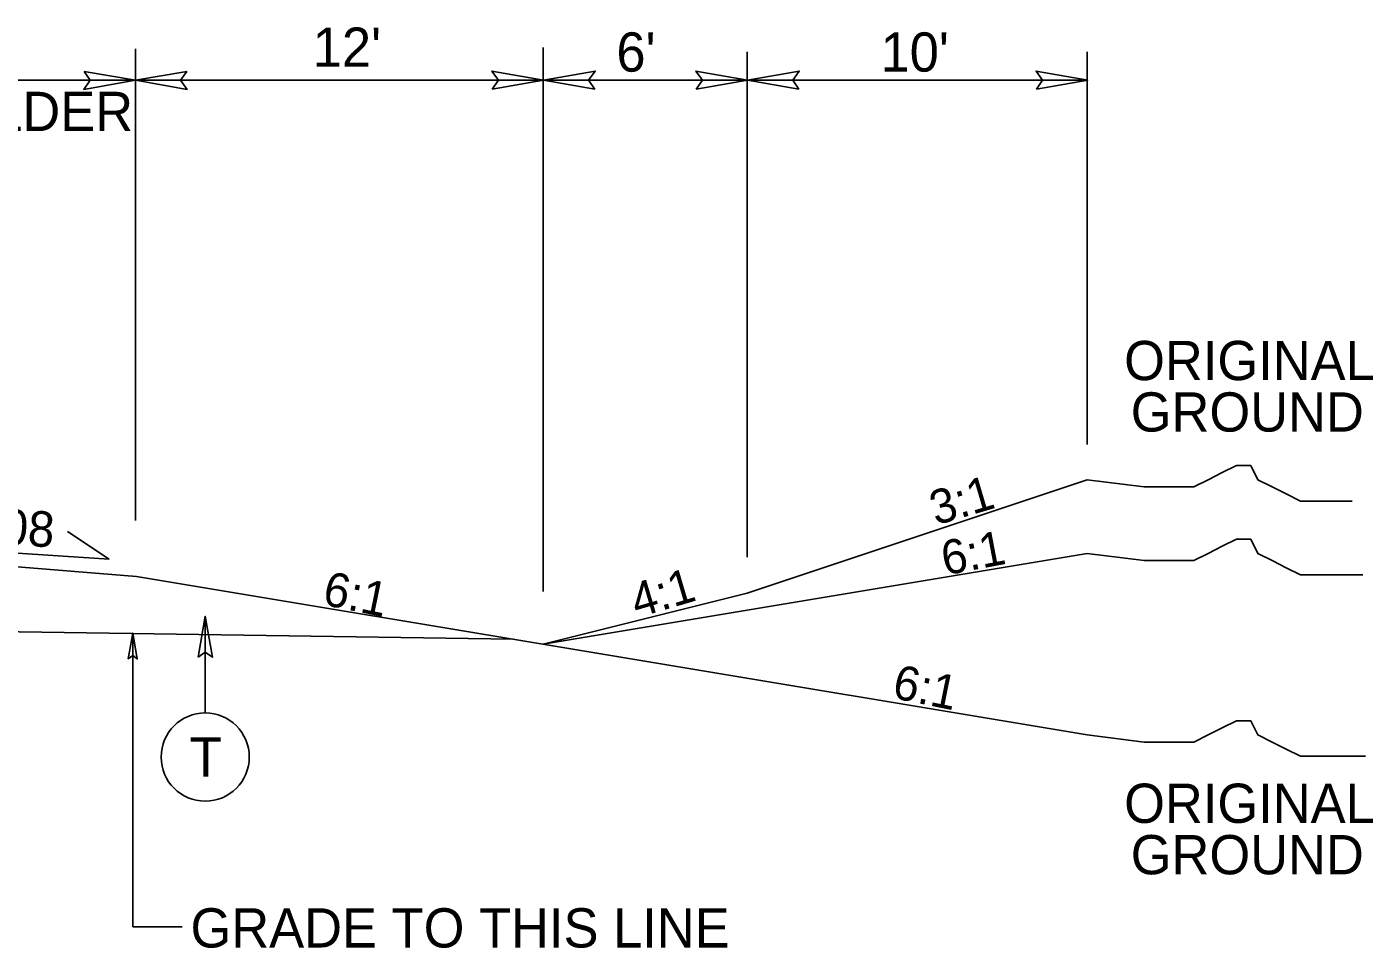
# Model space of a CAD drawing. Extents: x 2176024 to 2177225, y 75947 to 76635.
# Drawn here: x 2177062.27 to 2177101.85, y 76498.99 to 76526.06 of the extents above; entities that cross this region are included whole.
import ezdxf

# ---------------------------------------------------------------- set-up
doc = ezdxf.new("R2010")
doc.units = 0
for name, color, linetype in [('Old_Level_11', 7, 'Continuous'), ('Prop Dimension', 7, 'Continuous'), ('Typical Curb CELL', 7, 'Continuous'), ('Typical Pavement Slope CELL', 7, 'Continuous'), ('Typical Pavement Slope Information CELL', 7, 'Continuous'), ('Typical Shoulder Slope CELL', 7, 'Continuous'), ('Typical Slope Point Local CELL', 7, 'Continuous'), ('Typical Terminator CELL', 7, 'Continuous'), ('Typical Text General CELL', 7, 'Continuous')]:
    doc.layers.add(name, color=color, linetype=linetype)

msp = doc.modelspace()

# ---------------------------------------------------------------- linework, layer by layer
at = {"layer": 'Old_Level_11'}
msp.add_line((2177067.514, 76505.902), (2177067.514, 76508.744), dxfattribs=at)
msp.add_lwpolyline([(2177067.307, 76507.544), (2177067.514, 76508.744), (2177067.727, 76507.537), (2177067.514, 76507.691)], close=True, dxfattribs=at)
msp.add_circle((2177067.514, 76504.606), 1.296, dxfattribs=at)
at = {"layer": 'Prop Dimension'}
for p, q in [((2177065.462, 76511.553), (2177065.462, 76525.42)), ((2177077.449, 76509.465), (2177077.449, 76525.458)), ((2177083.449, 76510.483), (2177083.449, 76525.325)), ((2177093.449, 76513.785), (2177093.449, 76525.325)), ((2177065.462, 76524.493), (2177055.462, 76524.493)), ((2177065.462, 76524.493), (2177077.462, 76524.493)), ((2177077.462, 76524.493), (2177083.462, 76524.493)), ((2177083.462, 76524.493), (2177093.462, 76524.493)), ((2177065.382, 76508.249), (2177065.382, 76499.613)), ((2177066.836, 76499.613), (2177065.382, 76499.613))]:
    msp.add_line(p, q, dxfattribs=at)
at = {"layer": 'Typical Curb CELL'}
msp.add_line((2177076.565, 76508.068), (2177051.603, 76508.439), dxfattribs=at)
at = {"layer": 'Typical Pavement Slope CELL'}
for p, q in [((2177077.449, 76507.92), (2177093.449, 76510.587)), ((2177093.449, 76505.254), (2177065.497, 76509.912))]:
    msp.add_line(p, q, dxfattribs=at)
at = {"layer": 'Typical Pavement Slope Information CELL'}
for q in [(2177063.465, 76511.235), (2177059.944, 76510.729)]:
    msp.add_line((2177064.69, 76510.416), q, dxfattribs=at)
at = {"layer": 'Typical Shoulder Slope CELL'}
for p, q in [((2177083.449, 76509.42), (2177093.449, 76512.754)), ((2177059.462, 76510.395), (2177065.497, 76509.912)), ((2177077.449, 76507.92), (2177083.449, 76509.42))]:
    msp.add_line(p, q, dxfattribs=at)
at = {"layer": 'Typical Slope Point Local CELL'}
for points in [[(2177093.449, 76512.754), (2177095.12, 76512.546), (2177095.537, 76512.546), (2177096.165, 76512.546), (2177096.582, 76512.546), (2177097, 76512.754), (2177097.418, 76512.963), (2177097.835, 76513.173), (2177098.253, 76513.173), (2177098.463, 76512.754), (2177098.88, 76512.546), (2177099.298, 76512.336), (2177099.716, 76512.128), (2177100.133, 76512.128), (2177100.551, 76512.128), (2177100.969, 76512.128), (2177101.24, 76512.128)], [(2177093.449, 76510.587), (2177095.12, 76510.379), (2177095.538, 76510.379), (2177096.165, 76510.379), (2177096.583, 76510.379), (2177097, 76510.587), (2177097.418, 76510.797), (2177097.836, 76511.006), (2177098.253, 76511.006), (2177098.463, 76510.587), (2177098.881, 76510.379), (2177099.298, 76510.169), (2177099.716, 76509.961), (2177100.134, 76509.961), (2177100.551, 76509.961), (2177100.969, 76509.961), (2177101.387, 76509.961), (2177101.55, 76509.961)], [(2177093.449, 76505.254), (2177095.12, 76505.046), (2177095.537, 76505.046), (2177096.165, 76505.046), (2177096.582, 76505.046), (2177097, 76505.254), (2177097.418, 76505.463), (2177097.835, 76505.673), (2177098.253, 76505.673), (2177098.463, 76505.254), (2177098.88, 76505.046), (2177099.298, 76504.836), (2177099.716, 76504.628), (2177100.133, 76504.628), (2177100.551, 76504.628), (2177100.969, 76504.628), (2177101.386, 76504.628), (2177101.627, 76504.628)]]:
    msp.add_lwpolyline(points, dxfattribs=at)
at = {"layer": 'Typical Terminator CELL'}
for points in [[(2177063.952, 76524.752), (2177065.462, 76524.493), (2177063.944, 76524.224), (2177064.137, 76524.493)], [(2177066.972, 76524.752), (2177065.462, 76524.493), (2177066.98, 76524.224), (2177066.787, 76524.493)], [(2177075.952, 76524.233), (2177077.462, 76524.493), (2177075.944, 76524.761), (2177076.137, 76524.493)], [(2177078.972, 76524.233), (2177077.462, 76524.493), (2177078.98, 76524.761), (2177078.787, 76524.493)], [(2177081.952, 76524.233), (2177083.462, 76524.493), (2177081.944, 76524.761), (2177082.137, 76524.493)], [(2177084.972, 76524.233), (2177083.462, 76524.493), (2177084.98, 76524.761), (2177084.787, 76524.493)], [(2177091.952, 76524.233), (2177093.462, 76524.493), (2177091.944, 76524.761), (2177092.137, 76524.493)], [(2177065.252, 76507.494), (2177065.382, 76508.249), (2177065.516, 76507.49), (2177065.382, 76507.586)]]:
    msp.add_lwpolyline(points, close=True, dxfattribs=at)

# ---------------------------------------------------------------- texts
at = {"layer": 'Old_Level_11'}
msp.add_text('T', height=1.16, rotation=359.9997, dxfattribs=at).set_placement((2177067.057, 76504.026))
at = {"layer": 'Typical Pavement Slope Information CELL'}
msp.add_text('0.08', height=1.0429, rotation=356.2199, dxfattribs=at).set_placement((2177060.34, 76510.94))
at = {"layer": 'Typical Slope Point Local CELL'}
for s, rotation, p in [('3:1', 16.4649, (2177088.996, 76511.408)), ('6:1', 10.8168, (2177089.263, 76509.939)), ('6:1', 348.5135, (2177070.931, 76509.089)), ('4:1', 16.4649, (2177080.206, 76508.688)), ('6:1', 348.5135, (2177087.681, 76506.348))]:
    msp.add_text(s, height=1.0064, rotation=rotation, dxfattribs=at).set_placement(p)
at = {"layer": 'Typical Text General CELL'}
for s, height, p in [("12' ", 1.1533, (2177070.676, 76524.888)), ("6'", 1.1533, (2177079.604, 76524.745)), ("10'", 1.1533, (2177087.37, 76524.745)), ('SHOULDER', 1.1533, (2177056.825, 76523)), ('ORIGINAL', 1.1533, (2177094.532, 76515.68)), ('GROUND', 1.1533, (2177094.726, 76514.168)), ('ORIGINAL', 1.1533, (2177094.532, 76502.671)), ('GROUND', 1.1533, (2177094.726, 76501.16)), ('GRADE TO THIS LINE', 1.15334, (2177067.082, 76499.009))]:
    msp.add_text(s, height=height, dxfattribs=at).set_placement(p)

doc.saveas('drawing.dxf')
